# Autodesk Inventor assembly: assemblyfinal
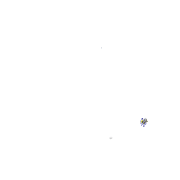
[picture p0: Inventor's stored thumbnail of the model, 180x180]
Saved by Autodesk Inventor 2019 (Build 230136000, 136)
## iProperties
Created: 2019-10
Part Number: assemblyfinal
Document SubType Name: Assembly
Designer: hp
Author: hp
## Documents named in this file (25)
- C:\Users\Hp\3D prototype\assemblyfinal.iam
- C:\Users\Hp\3D prototype\bolt.ipt
- C:\Users\Hp\3D prototype\roller base.ipt
- C:\Users\Hp\3D prototype\roller.ipt
- C:\Users\Hp\3D prototype\conveyer belt.ipt
- C:\Users\Hp\3D prototype\side motor stand.ipt
- C:\Users\Hp\3D prototype\motor supporter.ipt
- C:\Users\Hp\3D prototype\bolt clMP.ipt
- C:\Users\Hp\3D prototype\MOTOR STORER.ipt
- C:\Users\Hp\3D prototype\BOTTLE SUPPORTER.ipt
- C:\Users\Hp\3D prototype\BACKSTAND.ipt
- C:\Users\Hp\3D prototype\CAP STORER.ipt
- C:\Users\Hp\3D prototype\REALBOLTS.ipt
- C:\Users\Hp\3D prototype\0.3 INCH BOLTS.ipt
- C:\Users\Hp\3D prototype\0.3 INCH NUTS.ipt
- C:\Users\Hp\3D prototype\0.2 INCH MUTS.ipt
- C:\Users\Hp\3D prototype\chuck.ipt
- C:\Users\Hp\3D prototype\motor.ipt
- C:\Users\Hp\3D prototype\motor holder.ipt
- C:\Users\Hp\3D prototype\motorhanger.ipt
- C:\Users\Hp\3D prototype\0.2 top partscrew.ipt
- C:\Users\Hp\3D prototype\cap slider.ipt
- C:\Users\Hp\3D prototype\railing base.ipt
- C:\Users\Hp\3D prototype\conveyer sheet.ipt
- C:\Users\Hp\3D prototype\ORIGINAL SUPPORTER.0005.ipt
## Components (76 placed, 24 different names)
1. bolt:7
2. bolt:8
3. bolt:10
4. bolt:11
5. roller base:1
6. roller base:2
7. roller base:3
8. roller base:4
9. roller base:5
10. roller:2
11. roller:3
12. roller:4
13. roller:5
14. roller:6
15. conveyer belt:2
16. side motor stand:1 — Mate:12, Mate:17, Mate:20, Mate:29, Mate:35
17. side motor stand:2 — Mate:13, Mate:18, Mate:28, Mate:37
18. side motor stand:3 — Mate:10, Mate:30
19. side motor stand:4 — Mate:9, Mate:21, Mate:32, Mate:61
20. side motor stand:5 — Mate:14, Mate:19, Mate:27, Mate:36
21. motor supporter:2
22. bolt clMP:3
23. bolt clMP:5
24. bolt clMP:7
25. bolt clMP:8
26. bolt clMP:9
27. bolt clMP:12
28. side motor stand:6 — Mate:11, Mate:31
29. MOTOR STORER:1
30. BOTTLE SUPPORTER:1
31. BOTTLE SUPPORTER:3
32. BACKSTAND:1
33. BACKSTAND:2
34. motor supporter:6
35. CAP STORER:1
36. REALBOLTS:1 — Mate:10, Mate:30
37. REALBOLTS:2 — Mate:14, Mate:36
38. REALBOLTS:3 — Mate:9, Mate:32
39. REALBOLTS:4 — Mate:11, Mate:31
40. REALBOLTS:6 — Mate:12
41. REALBOLTS:8 — Mate:13, Mate:37
42. REALBOLTS:10 — Mate:46
43. 0.3 INCH BOLTS:3 — Mate:21, Mate:60
44. 0.3 INCH BOLTS:6 — Mate:20, Mate:35
45. 0.3 INCH BOLTS:7 — Mate:19, Mate:27, Mate:43
46. 0.3 INCH BOLTS:8 — Mate:18, Mate:28, Mate:44
47. 0.3 INCH BOLTS:9 — Mate:17, Mate:29
48. 0.3 INCH NUTS:1 — Mate:60
49. 0.3 INCH NUTS:5 — Mate:43
50. 0.3 INCH NUTS:7 — Mate:44
51. 0.2 INCH MUTS:3 — Mate:46
52. chuck:3
53. motor:1
54. motor holder:1
55. motorhanger:1
56. motor holder:2
57. cap slider:1
58. motor:2
59. motorhanger:4 — Mate:56, Mate:57, Mate:58, Mate:59
60. 0.2 top partscrew:11 — Mate:57
61. 0.2 top partscrew:12 — Mate:56
62. 0.2 top partscrew:13 — Mate:59
63. 0.2 top partscrew:14 — Mate:58
64. motor:8
65. motor:9
66. conveyer sheet:1
67. railing base:2
68. railing base:3
69. ORIGINAL SUPPORTER.0005:1
70. ORIGINAL SUPPORTER.0005:2
71. 0.3 INCH BOLTS:11
72. 0.3 INCH BOLTS:12
73. 0.3 INCH BOLTS:15 — Mate:61
74. railing base:4
75. MOTOR STORER:2
76. motorhanger:5
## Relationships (29: Mate 29)
- Mate:9: side motor stand:4 ↔ REALBOLTS:3
- Mate:10: side motor stand:3 ↔ REALBOLTS:1
- Mate:11: side motor stand:6 ↔ REALBOLTS:4
- Mate:12: side motor stand:1 ↔ REALBOLTS:6
- Mate:13: side motor stand:2 ↔ REALBOLTS:8
- Mate:14: side motor stand:5 ↔ REALBOLTS:2
- Mate:17: side motor stand:1 ↔ 0.3 INCH BOLTS:9
- Mate:18: side motor stand:2 ↔ 0.3 INCH BOLTS:8
- Mate:19: side motor stand:5 ↔ 0.3 INCH BOLTS:7
- Mate:20: side motor stand:1 ↔ 0.3 INCH BOLTS:6
- Mate:21: side motor stand:4 ↔ 0.3 INCH BOLTS:3
- Mate:27: side motor stand:5 ↔ 0.3 INCH BOLTS:7
- Mate:28: side motor stand:2 ↔ 0.3 INCH BOLTS:8
- Mate:29: side motor stand:1 ↔ 0.3 INCH BOLTS:9
- Mate:30: side motor stand:3 ↔ REALBOLTS:1
- Mate:31: side motor stand:6 ↔ REALBOLTS:4
- Mate:32: side motor stand:4 ↔ REALBOLTS:3
- Mate:35: side motor stand:1 ↔ 0.3 INCH BOLTS:6
- Mate:36: side motor stand:5 ↔ REALBOLTS:2
- Mate:37: side motor stand:2 ↔ REALBOLTS:8
- Mate:43: 0.3 INCH BOLTS:7 ↔ 0.3 INCH NUTS:5
- Mate:44: 0.3 INCH BOLTS:8 ↔ 0.3 INCH NUTS:7
- Mate:46: REALBOLTS:10 ↔ 0.2 INCH MUTS:3
- Mate:56: motorhanger:4 ↔ 0.2 top partscrew:12
- Mate:57: motorhanger:4 ↔ 0.2 top partscrew:11
- Mate:58: motorhanger:4 ↔ 0.2 top partscrew:14
- Mate:59: motorhanger:4 ↔ 0.2 top partscrew:13
- Mate:60: 0.3 INCH BOLTS:3 ↔ 0.3 INCH NUTS:1
- Mate:61: side motor stand:4 ↔ 0.3 INCH BOLTS:15
